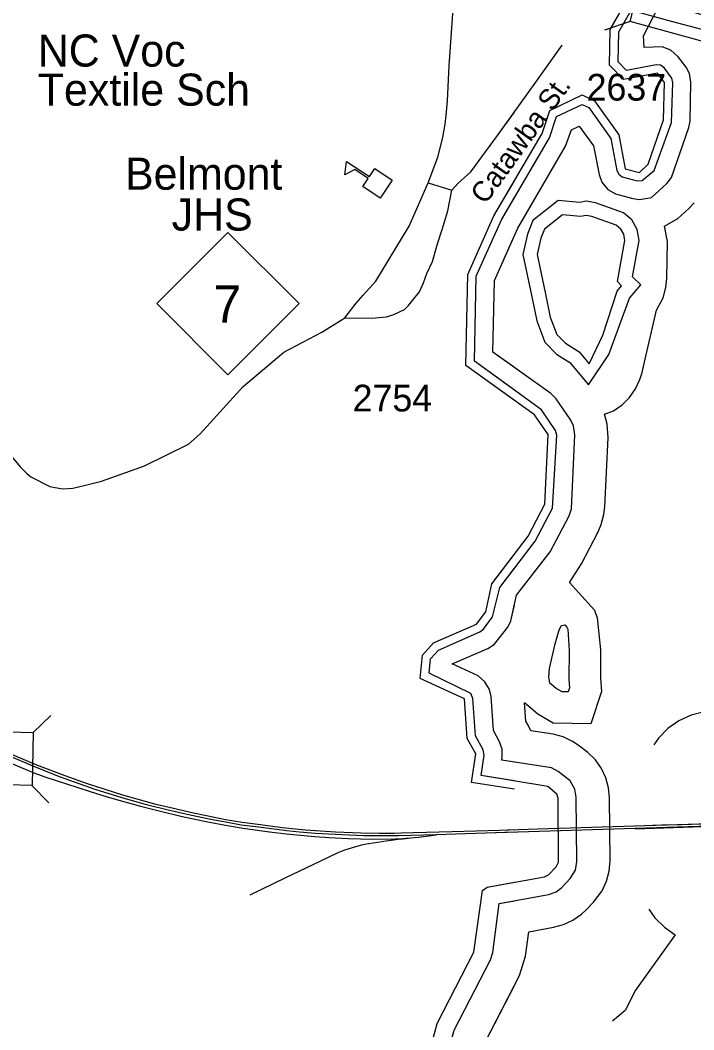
# Model space of a CAD drawing. Extents: x 1364363 to 1407445, y 538563 to 573342.
# Drawn here: x 1396708 to 1399857, y 545834 to 550556 of the extents above; entities that cross this region are included whole.
import ezdxf

# ---------------------------------------------------------------- set-up
doc = ezdxf.new("R2010")
doc.units = 0
for name, color, linetype in [('Default', 7, 'Continuous'), ('Exist Cultural Educational Facility High CELL', 7, 'Continuous'), ('Exist Cultural Educational Facility High Label', 7, 'Continuous'), ('Exist Hydrographic Buffer Line', 7, 'Continuous'), ('Exist Hydrographic Creek Double Shore', 7, 'Continuous'), ('Exist Hydrographic Island Shore', 7, 'Continuous'), ('Exist Railroad Mainline', 7, 'Continuous'), ('Exist Railroad Siding', 7, 'Continuous'), ('Exist Railroad Spur', 7, 'Continuous'), ('Exist Railroad Switch Yard', 7, 'Continuous'), ('Exist Road Primary NC Attributed', 7, 'Continuous'), ('Exist Road Primary NC Shield CELL', 7, 'Continuous'), ('Exist Road Primary NC Shield Number Label', 7, 'Continuous'), ('Exist Road Primary US Attributed', 7, 'Continuous'), ('Exist Road Primary US Structure Standard Bridge CELL', 7, 'Continuous'), ('Exist Road Secondary Type 51 Attributed', 7, 'Continuous'), ('Exist Road Secondary Type 51 Label', 7, 'Continuous'), ('Exist Road Secondary Type 51 Number Label', 7, 'Continuous')]:
    doc.layers.add(name, color=color, linetype=linetype)

msp = doc.modelspace()

# ---------------------------------------------------------------- linework, layer by layer
at = {"layer": 'Default'}
for p, q in [((1396851.1, 547303.6), (1396769.3, 547225.3)), ((1396851.1, 547303.6), (1396769.3, 547225.3)), ((1396763.3, 546977.5), (1396841.6, 546895.7)), ((1396763.3, 546977.5), (1396841.6, 546895.7))]:
    msp.add_line(p, q, dxfattribs=at)
msp.add_lwpolyline([(1396769.3, 547225.3), (1396763.9, 546977.5), (1396648.1, 546980), (1396653.5, 547227.8)], close=True, dxfattribs=at)
msp.add_lwpolyline([(1396769.3, 547225.3), (1396763.9, 546977.5), (1396648.1, 546980), (1396653.5, 547227.8)], close=True, dxfattribs=at)
at = {"layer": 'Exist Cultural Educational Facility High CELL'}
msp.add_lwpolyline([(1398391.3, 549723.5), (1398309.8, 549777.8), (1398335.4, 549816.1), (1398272.9, 549857.8), (1398226.6, 549832.1), (1398233.8, 549895.4), (1398340.7, 549824.1), (1398366.2, 549862.4), (1398447.7, 549808.1)], close=True, dxfattribs=at)
msp.add_lwpolyline([(1398391.3, 549723.5), (1398309.8, 549777.8), (1398335.4, 549816.1), (1398272.9, 549857.8), (1398226.6, 549832.1), (1398233.8, 549895.4), (1398340.7, 549824.1), (1398366.2, 549862.4), (1398447.7, 549808.1)], close=True, dxfattribs=at)
at = {"layer": 'Exist Hydrographic Buffer Line'}
for points in [[(1398189.2, 544104), (1398657.3, 545863.7), (1398829.2, 546197.6), (1398870.1, 546485.3), (1398892.2, 546501.6), (1399158.8, 546550.2), (1399177.5, 546558.9), (1399214.6, 546597.3), (1399225.1, 546618.1), (1399222.7, 546917.5), (1399217.4, 546937.1), (1399174.5, 546972.9), (1398863.3, 547023.9), (1398877.4, 547118.5), (1398872.9, 547143.6), (1398837, 547208.9), (1398824.6, 547384.2), (1398815.4, 547407.1), (1398620.4, 547501.8), (1398627.2, 547568.8), (1398663.8, 547610.5), (1398857.7, 547694.8), (1398873.9, 547707.7), (1398916.9, 547766), (1398950, 547903.2), (1399115.5, 548119.1), (1399197.3, 548274.4), (1399216.8, 548615.7), (1399211.4, 548637.5), (1399145.7, 548733.3), (1398832.2, 548960.7), (1398840.6, 549358), (1398958.4, 549622), (1399182.3, 550006.2), (1399216.3, 550105.1), (1399334.9, 550162), (1399366.3, 550147.2), (1399469.2, 550003), (1399497.5, 549853.5), (1399506.2, 549835.2), (1399523.1, 549823.3), (1399592.4, 549804.6), (1399616.4, 549805.6), (1399671.8, 549852.2), (1399753.7, 550077.4), (1399759.7, 550263.3), (1399754.4, 550284.2), (1399719.9, 550331.3), (1399701.4, 550345.1), (1399680.8, 550346.9), (1399542.4, 550321.1), (1399503.1, 550360.9), (1399506.5, 550501.2), (1399605.6, 550674)], [(1399659.9, 549727.3), (1399731.1, 549792.4), (1399753.2, 549820), (1399834.4, 550053.4), (1399839.8, 550084.1), (1399844, 550265.5), (1399837.3, 550306), (1399821.6, 550335.4), (1399785, 550385.1), (1399750.8, 550415.5), (1399709.4, 550430.5), (1399625.6, 550428.3), (1399622, 550483.1), (1399713.4, 550658.6)], [(1398737.4, 545832.8), (1398906.9, 546162.1), (1398917.3, 546195.5), (1398948.1, 546424.8), (1399178.1, 546467.1), (1399214, 546480.2), (1399239.9, 546500.5), (1399279.5, 546541.7), (1399303.8, 546581.1), (1399311, 546621.2), (1399307.9, 546922.2), (1399301, 546960.3), (1399279, 546998.5), (1399223.4, 547043), (1399192.7, 547059.5), (1398960, 547095.4), (1398962.2, 547109.5), (1398961.6, 547146.3), (1398949.3, 547181.2), (1398920.8, 547233.5), (1398909.4, 547393.4), (1398902.6, 547425.2), (1398881.2, 547462.3), (1398849.2, 547489.2), (1398728.3, 547545.6), (1398894.7, 547617.9), (1398923.8, 547636), (1398987.3, 547717.5), (1399002.7, 547746.6), (1399029.2, 547866.5), (1399185.4, 548070.3), (1399274.3, 548237.8), (1399285.4, 548270.4), (1399302, 548616.2), (1399295.6, 548658.9), (1399281.8, 548686), (1399213.7, 548784.9), (1399188.7, 548810.3), (1398918.4, 549003.8), (1398925.4, 549339), (1399034.3, 549583), (1399258.1, 549966.9), (1399285.3, 550043.7), (1399320.8, 550060.7), (1399388.9, 549968.4), (1399414.4, 549833.7), (1399427.9, 549797.8), (1399455.8, 549764.4), (1399491.8, 549743.7), (1399573.1, 549721.5), (1399603.7, 549717.4), (1399659.9, 549727.3)], [(1399018.9, 548825.3), (1398832.2, 548960.7), (1398840.6, 549358), (1398958.4, 549622), (1399018.9, 549725.8)], [(1399365.8, 548850), (1399460.3, 548991.8), (1399557.2, 549256), (1399609.5, 549318.5), (1399571, 549355.9), (1399601.4, 549525.5), (1399592.6, 549577.6), (1399567.2, 549621.9), (1399528.1, 549654.8), (1399397.7, 549701.8), (1399354.5, 549709.1), (1399324.7, 549703.9), (1399223.4, 549713.3), (1399104.9, 549618.4), (1399079.6, 549555.1), (1399058.5, 549460.1), (1399098.5, 549269.1), (1399123.2, 549149.4), (1399160.3, 549050.2), (1399216, 548994.5), (1399277.4, 548955.7), (1399365.8, 548850)], [(1399276, 547926.2), (1399332, 548013.8), (1399410, 548163.2), (1399424.9, 548197.1), (1399437.5, 548244.2), (1399441.5, 548279.9), (1399456.5, 548604.6), (1399452.5, 548666.2), (1399439.9, 548713.3), (1399482.7, 548729.5), (1399522.8, 548757.5), (1399557.3, 548792), (1399585.3, 548832), (1399605.9, 548876.2), (1399615.5, 548908.4), (1399629.8, 548970.3), (1399683.4, 549199.7), (1399713.9, 549258.1), (1399726.5, 549305.2), (1399730.6, 549347.4), (1399734.6, 549521.3), (1399720.5, 549593.2), (1399782.8, 549628.7), (1399834, 549675.3), (1399859.3, 549701.7)], [(1399018.9, 548931.9), (1398918.4, 549003.8), (1398925.4, 549339), (1399018.9, 549548.5)], [(1399018.9, 546998.4), (1398863.3, 547023.9), (1398877.4, 547118.5), (1398872.9, 547143.6), (1398837, 547208.9), (1398824.6, 547384.2), (1398815.4, 547407.1), (1398620.4, 547501.8), (1398627.2, 547568.8), (1398663.8, 547610.5), (1398857.7, 547694.8), (1398873.9, 547707.7), (1398916.9, 547766), (1398950, 547903.2), (1399018.9, 547993.1)], [(1399276, 547926.2), (1399392.5, 547796.3), (1399406, 547761)], [(1399018.9, 547086.3), (1398960, 547095.4), (1398962.2, 547109.5), (1398961.6, 547146.3), (1398949.3, 547181.2), (1398920.8, 547233.5), (1398909.4, 547393.4), (1398902.6, 547425.2), (1398881.2, 547462.3), (1398849.2, 547489.2), (1398728.3, 547545.6), (1398894.7, 547617.9), (1398923.8, 547636), (1398987.3, 547717.5), (1399002.7, 547746.6), (1399018.9, 547819.9)], [(1399406, 547761), (1399421.7, 547611.8), (1399420.9, 547479.5), (1399426, 547415.8), (1399376, 547264.5), (1399200.7, 547268), (1399128.4, 547310.2), (1399066.7, 547363)], [(1398882.5, 545776.8), (1399042.6, 546087.8), (1399071.3, 546178.8), (1399086.7, 546293), (1399201.9, 546314), (1399247.5, 546326.4), (1399291.7, 546347), (1399331.7, 546375), (1399353.7, 546395.7), (1399387.8, 546431.1), (1399428.3, 546485), (1399448.9, 546529.2), (1399461.5, 546576.4), (1399465.7, 546625), (1399462.7, 546920), (1399458.5, 546965.7), (1399445.9, 547012.8), (1399425.2, 547057.1), (1399397.2, 547097.1), (1399362.8, 547131.6), (1399317.3, 547165.8), (1399290.8, 547183.3), (1399246.5, 547203.9), (1399199.3, 547216.5), (1399095.5, 547232), (1399083.3, 547258.9), (1399072.7, 547278.2), (1399066.7, 547363)], [(1399905.2, 547321.5), (1399844.6, 547305.3), (1399787.7, 547278.8), (1399736.4, 547242.8), (1399692, 547198.4), (1399670.3, 547167.4)], [(1398169.4, 543584.2), (1398178.1, 543602.9), (1398150.1, 543804.4), (1398189.2, 544104), (1398657.3, 545863.7), (1398829.2, 546197.6), (1398870.1, 546485.3), (1398892.2, 546501.6), (1399018.9, 546524.7)], [(1397634.7, 544216.2), (1397648.2, 544199.9), (1397651.7, 544167.6), (1397662.3, 544131.6), (1397714.2, 544030.2), (1397781.6, 543779.2), (1397793.1, 543752.6), (1397933.6, 543520.7), (1397958.1, 543492.2), (1397995.7, 543470.4), (1398039.2, 543462.9), (1398167.7, 543487.9), (1398201.9, 543501), (1398235.2, 543528.9), (1398257, 543566.8), (1398264.5, 543609.1), (1398236.1, 543805.2), (1398272.8, 544087.5), (1398737.4, 545832.8), (1398906.9, 546162.1), (1398917.3, 546195.5), (1398948.1, 546424.8), (1399018.9, 546437.8)], [(1399647.8, 546398.7), (1399676, 546358.4), (1399720.4, 546314), (1399770.8, 546278.7), (1399584.7, 546019.1), (1399536.6, 545925), (1399477.7, 545874.5)], [(1398425, 544057.5), (1398882.5, 545776.8), (1399018.9, 546041.8)]]:
    msp.add_lwpolyline(points, dxfattribs=at)
at = {"layer": 'Exist Hydrographic Creek Double Shore'}
for points in [[(1398588.8, 547585.6), (1398639.8, 547643.7), (1398841.7, 547731.5), (1398884.8, 547789.7), (1398912.8, 547920.4), (1399083.8, 548143.5), (1399161.7, 548292.9), (1399176.8, 548617.5), (1399112.8, 548710.7), (1398791.8, 548940.4), (1398800.8, 549366.9), (1398922.7, 549640.2), (1399147.8, 550026.3), (1399183.8, 550133.8), (1399334.8, 550206.3), (1399392.8, 550178.9), (1399506.8, 550019), (1399536.8, 549860.9), (1399602.8, 549843.2), (1399644.8, 549881.7), (1399715.8, 550090.3), (1399719.8, 550264.2), (1399687.8, 550307.6), (1399528.8, 550277.9), (1399462.7, 550344.8), (1399466.8, 550512.2), (1399570.8, 550693.9)], [(1399018.9, 548777.9), (1398791.8, 548940.4), (1398800.8, 549366.9), (1398922.7, 549640.2), (1399018.9, 549805.2)], [(1398588.8, 547585.6), (1398639.8, 547643.7), (1398841.7, 547731.5), (1398884.8, 547789.7), (1398912.8, 547920.4), (1399018.9, 548058.8)], [(1399018.9, 546960.3), (1398817.7, 546990.2), (1398837.7, 547124.3), (1398797.7, 547197.3), (1398784.7, 547381.4), (1398577.7, 547477.5), (1398588.8, 547585.6)], [(1399018.9, 546960.3), (1398817.7, 546990.2), (1398837.7, 547124.3), (1398797.7, 547197.3), (1398784.7, 547381.4), (1398577.7, 547477.5), (1398588.8, 547585.6)]]:
    msp.add_lwpolyline(points, dxfattribs=at)
at = {"layer": 'Exist Hydrographic Island Shore'}
for points in [[(1399368.6, 548948.1), (1399432.7, 549083.2), (1399498.6, 549288.3), (1399520, 549313.9), (1399500.2, 549333.1), (1399534.8, 549525.9), (1399529.9, 549555.1), (1399516, 549579.2), (1399494.8, 549597), (1399381, 549638.1), (1399354.8, 549642.5), (1399327.4, 549637.7), (1399243.8, 549645.5), (1399159.4, 549577.9), (1399142.5, 549535.7), (1399125.6, 549459.7), (1399162.8, 549282.4), (1399186.4, 549167.6), (1399216.8, 549086.6), (1399257.3, 549046), (1399321.4, 549005.5), (1399368.6, 548948.1)], [(1399268.1, 547708.1), (1399274.1, 547607.8), (1399273.3, 547474.1), (1399276.4, 547433.9), (1399270, 547414.3), (1399242, 547414.8), (1399214.3, 547431), (1399184.9, 547456.2), (1399179.5, 547484.2), (1399182.2, 547523.6), (1399208.7, 547639.5), (1399228, 547704.8), (1399238.5, 547725.1), (1399254.6, 547728.9), (1399264.3, 547718), (1399268.1, 547708.1)]]:
    msp.add_lwpolyline(points, dxfattribs=at)
at = {"layer": 'Exist Railroad Mainline'}
for points in [[(1398654.5, 546746.1), (1398478, 546741.4), (1398314.6, 546741.4), (1398213.2, 546745.5), (1398088.8, 546752.9), (1398014.1, 546759.2), (1397954.3, 546765.5), (1397906.4, 546771.3), (1397821.9, 546781.3), (1397741.5, 546790.8), (1397685.8, 546802.8), (1397599.1, 546818.1), (1397502.8, 546838.6), (1397394.2, 546863.2), (1397298.5, 546886.9), (1397184.5, 546918.9), (1397059, 546958.3), (1396988, 546982.5), (1396892.5, 547017.2), (1396761.6, 547069.7), (1396666, 547110.7)], [(1398654.5, 546746.1), (1398478, 546741.4), (1398314.6, 546741.4), (1398213.2, 546745.5), (1398088.8, 546752.9), (1398014.1, 546759.2), (1397954.3, 546765.5), (1397906.4, 546771.3), (1397821.9, 546781.3), (1397741.5, 546790.8), (1397685.8, 546802.8), (1397599.1, 546818.1), (1397502.8, 546838.6), (1397394.2, 546863.2), (1397298.5, 546886.9), (1397184.5, 546918.9), (1397059, 546958.3), (1396988, 546982.5), (1396892.5, 547017.2), (1396761.6, 547069.7), (1396666, 547110.7)], [(1400230.1, 546795.5), (1399134.2, 546761.3), (1398885.1, 546754), (1398743.4, 546748.7), (1398654.5, 546746.1)], [(1399586, 546788.4), (1399706.6, 546792.2), (1399798.7, 546794.8), (1399897.3, 546797.8)], [(1399018.9, 546757.9), (1398885.1, 546754), (1398743.4, 546748.7), (1398654.5, 546746.1)]]:
    msp.add_lwpolyline(points, dxfattribs=at)
at = {"layer": 'Exist Railroad Siding'}
for points in [[(1396641.4, 547134.9), (1396784.8, 547073.4), (1396916.6, 547023.5), (1397021.1, 546985.7), (1397186.1, 546932.6), (1397335.8, 546890.6), (1397404.1, 546874.8), (1397518.7, 546848.6), (1397578.6, 546835.9), (1397668.4, 546818.1), (1397746.1, 546806), (1397831.7, 546793.9), (1397932.6, 546780.8), (1398041.4, 546770.3), (1398182.3, 546760.8), (1398301, 546755.5), (1398386.6, 546754), (1398456, 546754), (1398489.7, 546755), (1398546.4, 546756.6), (1398727.6, 546762.4), (1398948.8, 546768.7), (1399018.9, 546770.9)], [(1396641.4, 547134.9), (1396784.8, 547073.4), (1396916.6, 547023.5), (1397021.1, 546985.7), (1397186.1, 546932.6), (1397335.8, 546890.6), (1397404.1, 546874.8), (1397518.7, 546848.6), (1397578.6, 546835.9), (1397668.4, 546818.1), (1397746.1, 546806), (1397831.7, 546793.9), (1397932.6, 546780.8), (1398041.4, 546770.3), (1398182.3, 546760.8), (1398301, 546755.5), (1398386.6, 546754), (1398456, 546754), (1398489.7, 546755), (1398546.4, 546756.6), (1398727.6, 546762.4), (1398948.8, 546768.7), (1399128.4, 546774.5), (1400233.2, 546808.6)]]:
    msp.add_lwpolyline(points, dxfattribs=at)
at = {"layer": 'Exist Railroad Spur'}
for points in [[(1396661.7, 547083.4), (1396742.7, 547048.2), (1396772.2, 547035.9), (1396828.6, 547015.4), (1396919.7, 546985.9), (1397035.3, 546949.3), (1397115.6, 546924.1), (1397197.6, 546900.4), (1397270.6, 546879.5), (1397371.2, 546854.7), (1397460.1, 546833.8), (1397525.3, 546819.4), (1397586, 546806.9), (1397668, 546791.7), (1397750, 546777.7), (1397873.6, 546760.1), (1397953.1, 546750.8), (1398001, 546746.1), (1398085.5, 546738.9), (1398153.4, 546733.9), (1398241.1, 546729.5), (1398357.4, 546726), (1398462, 546727.4), (1398496.5, 546728.1), (1398522.8, 546730.3)], [(1396661.7, 547083.4), (1396742.7, 547048.2), (1396772.2, 547035.9), (1396828.6, 547015.4), (1396919.7, 546985.9), (1397035.3, 546949.3), (1397115.6, 546924.1), (1397197.6, 546900.4), (1397270.6, 546879.5), (1397371.2, 546854.7), (1397460.1, 546833.8), (1397525.3, 546819.4), (1397586, 546806.9), (1397668, 546791.7), (1397750, 546777.7), (1397873.6, 546760.1), (1397953.1, 546750.8), (1398001, 546746.1), (1398085.5, 546738.9), (1398153.4, 546733.9), (1398241.1, 546729.5), (1398357.4, 546726), (1398462, 546727.4), (1398496.5, 546728.1), (1398522.8, 546730.3)], [(1399582.8, 546774.2), (1399853, 546783.9), (1400027.1, 546788.4)], [(1398522.8, 546730.3), (1398550.4, 546733.5), (1398570.9, 546736), (1398654.5, 546746.1)], [(1398522.8, 546730.3), (1398550.4, 546733.5), (1398570.9, 546736), (1398654.5, 546746.1)]]:
    msp.add_lwpolyline(points, dxfattribs=at)
at = {"layer": 'Exist Railroad Switch Yard'}
msp.add_lwpolyline([(1398522.8, 546730.3), (1398464.8, 546722.7), (1398407.6, 546715.2), (1398369.3, 546709.5), (1398327.2, 546702.6), (1398303.4, 546697.9), (1398276, 546690.7), (1398255.9, 546684.6), (1398225, 546674.9), (1398193, 546662.3), (1398112.8, 546623.5), (1397944.8, 546543.3), (1397782, 546463.4)], dxfattribs=at)
msp.add_lwpolyline([(1398522.8, 546730.3), (1398464.8, 546722.7), (1398407.6, 546715.2), (1398369.3, 546709.5), (1398327.2, 546702.6), (1398303.4, 546697.9), (1398276, 546690.7), (1398255.9, 546684.6), (1398225, 546674.9), (1398193, 546662.3), (1398112.8, 546623.5), (1397944.8, 546543.3), (1397782, 546463.4)], dxfattribs=at)
at = {"layer": 'Exist Road Primary NC Attributed'}
for points in [[(1398615.2, 549794.7), (1398661, 549914.4), (1398684, 550007.8), (1398694.6, 550069.3), (1398700, 550109.4), (1398705.3, 550178.9), (1398714.5, 550342.3), (1398740.4, 550720.4), (1398742, 550742.3), (1398746.2, 550797.8)], [(1398615.2, 549794.7), (1398661, 549914.4), (1398684, 550007.8), (1398694.6, 550069.3), (1398700, 550109.4), (1398705.3, 550178.9), (1398714.5, 550342.3), (1398740.4, 550720.4), (1398742, 550742.3), (1398746.2, 550797.8)], [(1398226.3, 549164.2), (1398279.2, 549231.7), (1398312.3, 549269.9), (1398371.5, 549335.4), (1398527, 549592.2), (1398615.2, 549794.7)], [(1398226.3, 549164.2), (1398279.2, 549231.7), (1398312.3, 549269.9), (1398371.5, 549335.4), (1398527, 549592.2), (1398615.2, 549794.7)], [(1396561, 548642.8), (1396708.7, 548467), (1396740.2, 548435.9), (1396758.1, 548420.7), (1396847.2, 548374.8), (1396905.7, 548364.6), (1396954.1, 548367.2), (1397007.5, 548379.9), (1397089, 548400.3), (1397289.5, 548471.6), (1397495.3, 548573.1), (1397550.2, 548621.9), (1397750.3, 548843.5), (1397941.2, 549004), (1398118.8, 549096.7), (1398226.3, 549164.2)], [(1396561, 548642.8), (1396708.7, 548467), (1396740.2, 548435.9), (1396758.1, 548420.7), (1396847.2, 548374.8), (1396905.7, 548364.6), (1396954.1, 548367.2), (1397007.5, 548379.9), (1397089, 548400.3), (1397289.5, 548471.6), (1397495.3, 548573.1), (1397550.2, 548621.9), (1397750.3, 548843.5), (1397941.2, 549004), (1398118.8, 549096.7), (1398226.3, 549164.2)]]:
    msp.add_lwpolyline(points, dxfattribs=at)
at = {"layer": 'Exist Road Primary NC Shield CELL'}
msp.add_lwpolyline([(1397346.8, 549230.5), (1397679.8, 549563.5), (1398012.8, 549230.5), (1397679.8, 548897.5)], close=True, dxfattribs=at)
msp.add_lwpolyline([(1397346.8, 549230.5), (1397679.8, 549563.5), (1398012.8, 549230.5), (1397679.8, 548897.5)], close=True, dxfattribs=at)
at = {"layer": 'Exist Road Primary US Attributed'}
msp.add_lwpolyline([(1399468.3, 550629.3), (1399751.3, 550551), (1400177.6, 550439.5)], dxfattribs=at)
at = {"layer": 'Exist Road Primary US Structure Standard Bridge CELL'}
msp.add_line((1399560.4, 550550.3), (1399439.3, 550508.3), dxfattribs=at)
msp.add_lwpolyline([(1400822.7, 550309.8), (1400792.1, 550190.3), (1400333.9, 550326.3), (1400075.8, 550407.5), (1399560.4, 550550.3), (1399591.1, 550672.7)], close=True, dxfattribs=at)
at = {"layer": 'Exist Road Secondary Type 51 Attributed'}
msp.add_line((1398615.2, 549794.7), (1398726.7, 549760.8), dxfattribs=at)
msp.add_line((1398615.2, 549794.7), (1398726.7, 549760.8), dxfattribs=at)
for points in [[(1398726.7, 549760.8), (1398756.1, 549792.9), (1398814.9, 549846.3), (1398940.4, 550016.3), (1399111.4, 550254.3), (1399242.3, 550438.7)], [(1398726.7, 549760.8), (1398756.1, 549792.9), (1398814.9, 549846.3), (1398940.4, 550016.3), (1399018.9, 550125.6)], [(1398226.3, 549164.2), (1398352, 549161.7), (1398420.2, 549168.1), (1398454.4, 549179.4), (1398504.9, 549202.4), (1398523.7, 549220.8), (1398542.4, 549244.8), (1398574.4, 549284.9), (1398593.1, 549327.7), (1398609.2, 549370.5), (1398635.9, 549426.6), (1398659.9, 549509.5), (1398681.3, 549576.3), (1398708, 549664.5), (1398726.7, 549760.8)], [(1398226.3, 549164.2), (1398352, 549161.7), (1398420.2, 549168.1), (1398454.4, 549179.4), (1398504.9, 549202.4), (1398523.7, 549220.8), (1398542.4, 549244.8), (1398574.4, 549284.9), (1398593.1, 549327.7), (1398609.2, 549370.5), (1398635.9, 549426.6), (1398659.9, 549509.5), (1398681.3, 549576.3), (1398708, 549664.5), (1398726.7, 549760.8)]]:
    msp.add_lwpolyline(points, dxfattribs=at)

# ---------------------------------------------------------------- texts
at = {"layer": 'Exist Cultural Educational Facility High Label'}
for s, p in [('NC Voc', (1396790.5, 550338.8)), ('NC Voc', (1396790.5, 550338.8)), ('Textile Sch', (1396790.5, 550156)), ('Textile Sch', (1396790.5, 550156))]:
    msp.add_text(s, height=150, dxfattribs=at).set_placement(p)
for s, p in [('Belmont', (1397198.3, 549763)), ('Belmont', (1397198.3, 549763)), ('JHS', (1397416.5, 549572)), ('JHS', (1397416.5, 549572))]:
    msp.add_text(s, height=150, rotation=0, dxfattribs=at).set_placement(p)
at = {"layer": 'Exist Road Primary NC Shield Number Label'}
msp.add_text('7', height=175, dxfattribs=at).set_placement((1397611.9, 549140.8))
msp.add_text('7', height=175, dxfattribs=at).set_placement((1397611.9, 549140.8))
at = {"layer": 'Exist Road Secondary Type 51 Label'}
msp.add_text('Catawba St.', height=95, rotation=54.2998, dxfattribs=at).set_placement((1398883.5, 549690))
msp.add_text('Catawba St.', height=95, rotation=54.2998, dxfattribs=at).set_placement((1398883.5, 549690))
at = {"layer": 'Exist Road Secondary Type 51 Number Label'}
for s, p in [('2637', (1399356.3, 550179.7)), ('2754', (1398262.4, 548726)), ('2754', (1398262.4, 548726))]:
    msp.add_text(s, height=125, dxfattribs=at).set_placement(p)

doc.saveas('drawing.dxf')
